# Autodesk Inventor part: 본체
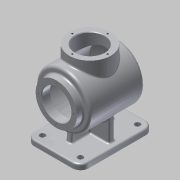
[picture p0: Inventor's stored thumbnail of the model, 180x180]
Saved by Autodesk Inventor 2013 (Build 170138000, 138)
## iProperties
Created: 2016-09
Part Number: 본체
Material: 알루미늄 6061
Document SubType Name: Modeling
Designer: Administrator
Mass: 941.493 g
Surface Area: 1328.18 cm^2
Volume: 347.415 cm^3
Density: 2.71 g/cm^3
Author: Administrator
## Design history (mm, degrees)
sketch "스케치3"
  geometry: C1 r 50 at (0, 0); 1 further point
  constraints: 1 centre point, 1 coincident
  dimensions: "d2" = 100 diameter of C1
extrude "돌출1" new body sketch "스케치3" distance "d4" = 110; taper "d5" = 0 deg
node "작업 평면1"
sketch "스케치4"
  geometry: L1 (0, 50)-(110, 50) reference; L2 (110, -50)-(110, 50) reference; L3 (0, 0)-(110, 0); A1 r 115 centre (-5, 0) between (110, 0) and (98.562, 50)
  constraints: 2 end point, 2 point on circle, 1 centre point, 1 midpoint, 1 point on line, 1 tangent
  dimensions: "d17" = 115 radius of A1
revolve "회전1" sketch "스케치4" stored, may be unused: angle "d19" = 90 deg
sketch "스케치5"
  geometry: C1 r 50 at (0, 0) reference; C2 r 38 at (0, 0)
  constraints: 1 centre point, 1 coincident
  dimensions: "d20" = 76 diameter of C2
extrude "돌출2" join sketch "스케치5" distance "d22" = 12; taper "d23" = 0 deg
sketch "스케치6"
  geometry: C1 r 38 at (0, 0) reference; C2 r 27 at (0, 0)
  constraints: 1 centre point, 1 coincident
  dimensions: "d24" = 54 diameter of C2
extrude "돌출3" cut sketch "스케치6" distance "d26" = 15; taper "d27" = 0 deg
feature "쉘1" dims "d28" = 3
node "작업 평면2"
sketch "스케치7"
  geometry: L1 (-50, 98.562)-(50, 98.562) reference; L2 (-50, 0)-(50, 0) reference; L3 (-38, -12)-(38, -12) reference; L4 (-50, 0)-(-50, 98.562) reference; L5 (50, 0)-(50, 98.562) reference; L6 (-50, 50)-(50, 50); C1 r 38 at (0, 50); A1 r 115 centre (0, -5) between (50, 98.562) and (-50, 98.562) reference; 1 further point
  constraints: 2 end point, 2 point on line, 1 centre point, 1 midpoint, 1 perpendicular
  dimensions: "d32" = 62 distance between parallel lines of L3 L6; "d33" = 76 diameter of C1
extrude "돌출4" join sketch "스케치7" stored distance "d34" = 15; taper "d35" = 0 deg
sketch "스케치8"
  geometry: C1 r 38 at (0, 0) reference; C2 r 27 at (0, 0); 1 further point
  constraints: 1 centre point, 1 coincident
  dimensions: "d36" = 54 diameter of C2
extrude "돌출5" cut sketch "스케치8" stored distance "d38" = 15; taper "d39" = 0 deg
node "작업 평면3"
sketch "스케치9"
  geometry: L1 (-38, -12)-(38, -12) reference; L2 (-50, 117.5)-(50, 117.5); L3 (50, 117.5)-(50, -17.5); L4 (50, -17.5)-(-50, -17.5); L5 (-50, -17.5)-(-50, 117.5); L6 (-50, 50)-(50, 50); L7 (0, -17.5)-(0, 117.5); 1 further point
  constraints: 12 end point, 4 midpoint, 2 parallel, 1 horizontal, 1 perpendicular
  dimensions: "d41" = 62 distance between parallel lines of L1 L6; "d42" = 135 distance between parallel lines of L4 L2; "d43" = 100 distance between parallel lines of L3 L5; "d44" = 0 distance from line of point (0, 0) L7
extrude "돌출6" join sketch "스케치9" distance "d45" = 10; taper "d46" = 0 deg
sketch "스케치10"
  geometry: L1 (50, 117.5)-(-50, 117.5) reference; L2 (-50, 117.5)-(-50, -17.5) reference; L3 (-50, -17.5)-(50, -17.5) reference; L4 (50, -17.5)-(50, 117.5) reference; L5 (-50, 50)-(50, 50); L6 (-40, 45)-(40, 45); L7 (40, 45)-(40, 55.293); L8 (40, 55.293)-(-40, 55.293); L9 (-40, 55.293)-(-40, 45); L10 (0, 117.5)-(0, -17.5); 1 further point
  constraints: 12 end point, 4 midpoint, 2 parallel, 1 horizontal, 1 perpendicular
  dimensions: "d61" = 5 distance between parallel lines of L5 L6; "d63" = 10.29335 distance between parallel lines of L6 L8; "d64" = 40 distance between parallel lines of L7 L10; "d65" = 40 distance between parallel lines of L9 L10
extrude "돌출7" join sketch "스케치10" stored distance "d66" = 10; taper "d67" = 0 deg
node "작업 평면5"
sketch "스케치15" dims "d100" = 65
  geometry: C1 r 27 at (0, 0) reference; C2 r 38 at (0, 0) reference; C3 r 2 at (0, 32.5); 2 further points
  constraints: 2 vertical alignment, 1 centre point, 1 coincident, 2 other
  dimensions: "d102" = 4 diameter of C3
hole "구멍2" sketch "스케치15" at (0, 32.5) diameter "d103" = 3.242; stored, may be unused: countersink angle "d107" = 90 deg, drill point angle "d109" = 118 deg; dims "d104" = 8, "d105" = 4, "d106" = 2, "d108" = 10
node "작업 평면6"
sketch "스케치16"
  geometry: L1 (-29.035, 4.203)-(29.035, 4.203); L2 (29.035, 4.203)-(29.035, -4.203); L3 (29.035, -4.203)-(-29.035, -4.203); L4 (-29.035, -4.203)-(-29.035, 4.203); L5 (-29.035, 0)-(29.035, 0); L6 (0, 4.203)-(0, -4.203); 1 further point
  constraints: 4 end point, 4 midpoint, 2 other
  dimensions: "d114" = 0 distance from line of point (0, 0) L6; "d115" = 0 distance from line of point (0, 0) L5
feature "엠보싱1" sketch "스케치16" dims "d2" = 100, "d116" = 0.5, "d117" = 0
fillet "모깎기1" dims "d118" = 2
chamfer "모따기1" distance "d119" = 1; stored, may be unused: second distance "d120" = 2, angle "d121" = 45 deg
fillet "모깎기2" dims "d122" = 5
fillet "모깎기3" dims "d123" = 3
fillet "모깎기4" dims "d124" = 3
fillet "모깎기5" dims "d125" = 15
sketch "스케치17"
  geometry: C1 r 5 at (-35, -2.5); C2 r 5 at (-35, 102.5); C3 r 5 at (35, 102.5); C4 r 5 at (35, -2.5); A1 r 15 centre (-35, 102.5) between (-35, 117.5) and (-50, 102.5) reference; A2 r 15 centre (-35, -2.5) between (-50, -2.5) and (-35, -17.5) reference; A3 r 15 centre (35, -2.5) between (35, -17.5) and (50, -2.5) reference; A4 r 15 centre (35, 102.5) between (50, 102.5) and (35, 117.5) reference; 1 further point
  constraints: 4 centre point, 4 coincident, 3 equal radius
  dimensions: "d126" = 10 diameter of C1
extrude "돌출9" cut sketch "스케치17" stored distance "d128" = 10; taper "d129" = 0 deg
fillet "모깎기6" dims "d130" = 3
node "작업 평면7"
sketch "스케치18"
  geometry: L1 (12.187, -47)-(10, -72); L2 (-2.5, -72)-(102.5, -72) reference; L3 (5, -47)-(95.374, -47) reference; L4 (50, -47)-(50, -72); L5 (-12, 28)-(-12, -28) reference; L6 (12.187, -47)-(50, -47); 1 further point
  constraints: 6 end point, 2 point on line, 1 collinear, 1 midpoint, 1 perpendicular
  dimensions: "d132" = 0 distance from line of L2 L1.end; "d133" = 95 deg angle of L2 L1; "d134" = 62 distance between parallel lines of L5 L4; "d135" = 40 distance from line of L1.end L4
feature "리브1" sketch "스케치18" dims "d136" = 1, "d137" = 10, "d138" = 0, "d139" = 0, "d140" = 1, "d141" = 1
sketch "스케치19"
  geometry: L1 (5, -47)-(95.374, -47) reference; L2 (87.813, -47)-(90, -72); L3 (-12, 28)-(-12, -28) reference; L4 (-2.5, -72)-(102.5, -72) reference; L5 (50, -47)-(87.813, -47); L6 (50, -47)-(50, -72); 1 further point
  constraints: 6 end point, 2 point on line, 1 collinear, 1 midpoint
  dimensions: "d143" = 0 distance from line of L4 L2.end; "d144" = 95 deg angle of L4 L2; "d147" = 25 distance of L5.start L6.end; "d148" = 40 distance from line of L6 L2.end
feature "리브2" sketch "스케치19" dims "d149" = 1, "d150" = 10, "d151" = 0, "d152" = 0, "d153" = 1, "d154" = 1
fillet "모깎기7" dims "d155" = 3
fillet "모깎기8" dims "d156" = 3
sketch "스케치20"
  geometry: C1 r 30 at (0, 0) reference; C2 r 35 at (0, 0) reference
extrude "돌출10" join sketch "스케치20" stored distance "d157" = 10; taper "d158" = 0 deg
sketch "스케치21" dims "d159" = 65
  geometry: C1 r 38 at (0, 0) reference; C2 r 28 at (0, 0) reference; C3 r 2 at (0, 32.5); 1 further point
  constraints: 2 vertical alignment, 1 centre point, 1 coincident, 2 other
  dimensions: "d161" = 4 diameter of C3
hole "구멍3" sketch "스케치21" at (0, 32.5) diameter "d162" = 3.242; stored, may be unused: countersink angle "d166" = 90 deg, drill point angle "d168" = 118 deg; dims "d163" = 8, "d164" = 4, "d165" = 2, "d167" = 10
node "솔리드1"
pattern_circular "원형 패턴2" dims angle "d111" = 360 deg
pattern_circular "원형 패턴3" dims angle "d170" = 360 deg
node "투영된 루프1"
other parameters: "d6" = 0, "d29" = 65, "d40" = -82, "d77" = 0, "d113" = 229.5, "d131" = 0
